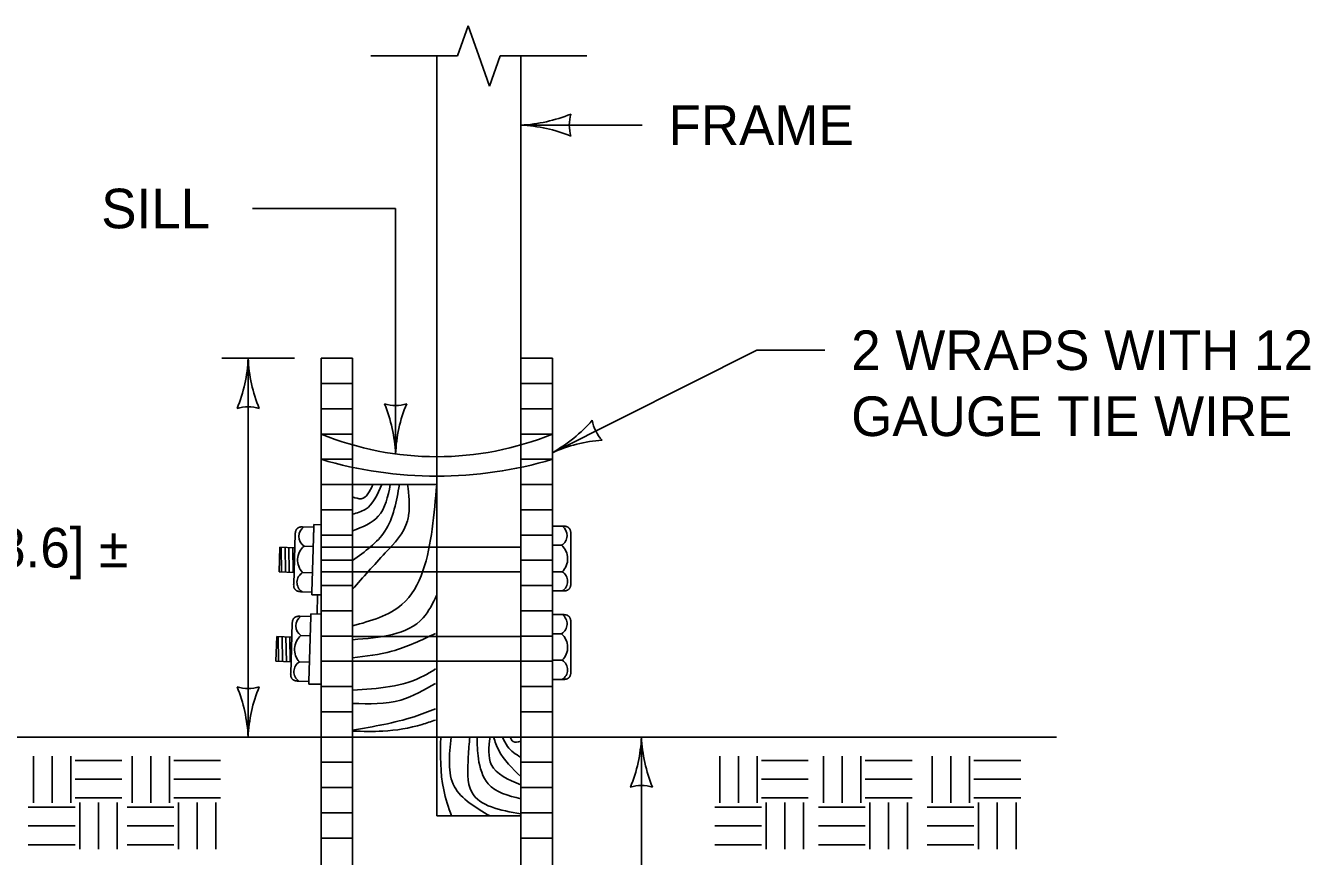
# Model space of a CAD drawing. Extents: x 49991.4 to 50021, y 49987.6 to 50011.4.
# Drawn here: x 50010.642 to 50012.589, y 49992.32 to 49993.578 of the extents above; entities that cross this region are included whole.
import ezdxf

# ---------------------------------------------------------------- set-up
doc = ezdxf.new("R2010")
doc.units = 0
for name, color, linetype in [('Level 1', 7, 'Continuous'), ('Level 2', 7, 'Continuous'), ('Level 3', 7, 'Continuous'), ('Level 4', 7, 'Continuous'), ('Level 6', 7, 'Continuous')]:
    doc.layers.add(name, color=color, linetype=linetype)

msp = doc.modelspace()

# ---------------------------------------------------------------- linework, layer by layer
at = {"layer": 'Level 1'}
for p, q in [((50011.265, 49992.8828), (50011.265, 49993.5322)), ((50011.3925, 49993.0741), (50011.3925, 49993.5322)), ((50011.1376, 49993.0741), (50011.0897, 49993.0741)), ((50011.0897, 49993.0741), (50011.0898, 49991.5441)), ((50011.1376, 49993.0741), (50011.0898, 49993.0741)), ((50011.1376, 49993.0741), (50011.1376, 49991.5441)), ((50011.3925, 49993.0741), (50011.3925, 49991.5441)), ((50011.4403, 49993.0741), (50011.3925, 49993.0741)), ((50011.4403, 49993.0741), (50011.4403, 49991.5441)), ((50011.1376, 49993.0358), (50011.0897, 49993.0358)), ((50011.4403, 49993.0358), (50011.3925, 49993.0358)), ((50011.1376, 49992.9976), (50011.0897, 49992.9976)), ((50011.4403, 49992.9976), (50011.3925, 49992.9976)), ((50011.1376, 49992.9593), (50011.0897, 49992.9593)), ((50011.4403, 49992.9593), (50011.3925, 49992.9593)), ((50011.1376, 49992.9211), (50011.0897, 49992.9211)), ((50011.4403, 49992.9211), (50011.3925, 49992.9211)), ((50011.265, 49992.8828), (50011.0897, 49992.8828)), ((50011.1376, 49992.8828), (50011.0898, 49992.8828)), ((50011.265, 49992.5003), (50011.265, 49992.8828)), ((50011.4403, 49992.8828), (50011.3925, 49992.8828)), ((50011.1376, 49992.8446), (50011.0897, 49992.8446)), ((50011.4403, 49992.8446), (50011.3925, 49992.8446)), ((50011.079, 49992.8225), (50011.0788, 49992.8181)), ((50011.079, 49992.8223), (50011.0897, 49992.8219)), ((50011.4403, 49992.8334), (50011.4403, 49992.5245)), ((50011.4403, 49992.8198), (50011.4403, 49992.7217)), ((50011.4572, 49992.8198), (50011.4403, 49992.8198)), ((50011.0482, 49992.7319), (50011.0506, 49992.808)), ((50011.0618, 49992.8188), (50011.0788, 49992.8181)), ((50011.0788, 49992.8181), (50011.0758, 49992.72)), ((50011.0785, 49992.8101), (50011.0783, 49992.8099)), ((50011.1376, 49992.8063), (50011.0897, 49992.8063)), ((50011.4403, 49992.8063), (50011.3925, 49992.8063)), ((50011.4682, 49992.7326), (50011.4682, 49992.8087)), ((50011.0272, 49992.7878), (50011.026, 49992.7504)), ((50011.0499, 49992.7871), (50011.0272, 49992.7878)), ((50011.0292, 49992.7877), (50011.0297, 49992.7503)), ((50011.0352, 49992.7876), (50011.0357, 49992.7501)), ((50011.0411, 49992.7874), (50011.0416, 49992.7499)), ((50011.0471, 49992.7872), (50011.0476, 49992.7497)), ((50011.0639, 49992.7896), (50011.0779, 49992.7891)), ((50011.4544, 49992.7909), (50011.4403, 49992.7909)), ((50011.1376, 49992.7681), (50011.0897, 49992.7681)), ((50011.4403, 49992.7681), (50011.3925, 49992.7681)), ((50011.0488, 49992.7497), (50011.026, 49992.7504)), ((50011.0767, 49992.749), (50011.0617, 49992.7495)), ((50011.4403, 49992.7506), (50011.4553, 49992.7506)), ((50011.1376, 49992.7298), (50011.0897, 49992.7298)), ((50011.4403, 49992.7298), (50011.3925, 49992.7298)), ((50011.4403, 49992.7217), (50011.4572, 49992.7217)), ((50011.0758, 49992.72), (50011.0588, 49992.7205)), ((50011.0758, 49992.72), (50011.0756, 49992.7157)), ((50011.0756, 49992.7157), (50011.0897, 49992.7158)), ((50011.084, 49992.6866), (50011.0845, 49992.7158)), ((50011.0573, 49992.6833), (50011.0743, 49992.6828)), ((50011.0743, 49992.6828), (50011.0712, 49992.5847)), ((50011.0744, 49992.687), (50011.0743, 49992.6828)), ((50011.0744, 49992.687), (50011.0897, 49992.6864)), ((50011.1376, 49992.6916), (50011.0897, 49992.6916)), ((50011.4403, 49992.6916), (50011.3925, 49992.6916)), ((50011.4403, 49992.6858), (50011.4403, 49992.5876)), ((50011.4572, 49992.6858), (50011.4403, 49992.6858)), ((50011.0437, 49992.5966), (50011.046, 49992.6727)), ((50011.4682, 49992.5986), (50011.4682, 49992.6748)), ((50011.0226, 49992.6525), (50011.0214, 49992.6151)), ((50011.0454, 49992.6518), (50011.0226, 49992.6525)), ((50011.0246, 49992.6524), (50011.0253, 49992.6149)), ((50011.0306, 49992.6523), (50011.0311, 49992.6147)), ((50011.0365, 49992.6521), (50011.0372, 49992.6145)), ((50011.0425, 49992.6519), (50011.043, 49992.6143)), ((50011.0593, 49992.6543), (50011.0734, 49992.6538)), ((50011.1376, 49992.6533), (50011.0897, 49992.6533)), ((50011.4403, 49992.6533), (50011.3925, 49992.6533)), ((50011.4544, 49992.6568), (50011.4403, 49992.6568)), ((50011.0442, 49992.6142), (50011.0214, 49992.6151)), ((50011.0721, 49992.6136), (50011.0571, 49992.6141)), ((50011.1376, 49992.6151), (50011.0897, 49992.6151)), ((50011.4403, 49992.6151), (50011.3925, 49992.6151)), ((50011.4403, 49992.6166), (50011.4553, 49992.6166)), ((50011.0712, 49992.5847), (50011.0542, 49992.5852)), ((50011.4403, 49992.5876), (50011.4572, 49992.5876)), ((50011.0712, 49992.5847), (50011.071, 49992.5804)), ((50011.071, 49992.5804), (50011.0897, 49992.5803)), ((50011.1376, 49992.5768), (50011.0897, 49992.5768)), ((50011.4403, 49992.5768), (50011.3925, 49992.5768)), ((50011.1376, 49992.5386), (50011.0897, 49992.5386)), ((50011.4403, 49992.5386), (50011.3925, 49992.5386)), ((50011.0897, 49992.5003), (50010.4249, 49992.5003)), ((50011.1376, 49992.5003), (50011.0897, 49992.5003)), ((50011.1376, 49992.5003), (50011.3925, 49992.5003)), ((50011.1376, 49992.5003), (50011.265, 49992.5003)), ((50011.265, 49992.5003), (50011.265, 49992.3808)), ((50012.2044, 49992.5003), (50011.3925, 49992.5003)), ((50010.6537, 49992.4715), (50010.6537, 49992.4006)), ((50010.682, 49992.4715), (50010.682, 49992.4006)), ((50010.7104, 49992.4715), (50010.7104, 49992.4006)), ((50010.8034, 49992.4715), (50010.8034, 49992.4006)), ((50010.8317, 49992.4715), (50010.8317, 49992.4006)), ((50010.8601, 49992.4715), (50010.8601, 49992.4006)), ((50011.6942, 49992.4715), (50011.6942, 49992.4006)), ((50011.7225, 49992.4715), (50011.7225, 49992.4006)), ((50011.7509, 49992.4715), (50011.7509, 49992.4006)), ((50011.8513, 49992.4715), (50011.8513, 49992.4006)), ((50011.8796, 49992.4715), (50011.8796, 49992.4006)), ((50011.908, 49992.4715), (50011.908, 49992.4006)), ((50012.0161, 49992.4715), (50012.0161, 49992.4006)), ((50012.0444, 49992.4715), (50012.0444, 49992.4006)), ((50012.0728, 49992.4715), (50012.0728, 49992.4006)), ((50010.7169, 49992.4649), (50010.7878, 49992.4649)), ((50010.8666, 49992.4649), (50010.9375, 49992.4649)), ((50011.1376, 49992.4621), (50011.0897, 49992.4621)), ((50011.4403, 49992.4621), (50011.3925, 49992.4621)), ((50011.7574, 49992.4649), (50011.8283, 49992.4649)), ((50011.9146, 49992.4649), (50011.9855, 49992.4649)), ((50012.0793, 49992.4649), (50012.1502, 49992.4649)), ((50010.7169, 49992.4366), (50010.7878, 49992.4366)), ((50010.8666, 49992.4366), (50010.9375, 49992.4366)), ((50011.7574, 49992.4366), (50011.8283, 49992.4366)), ((50011.9146, 49992.4366), (50011.9855, 49992.4366)), ((50012.0793, 49992.4366), (50012.1502, 49992.4366)), ((50011.1376, 49992.4238), (50011.0897, 49992.4238)), ((50011.4403, 49992.4238), (50011.3925, 49992.4238)), ((50010.646, 49992.394), (50010.7169, 49992.394)), ((50010.7169, 49992.4082), (50010.7878, 49992.4082)), ((50010.724, 49992.4011), (50010.724, 49992.3303)), ((50010.7524, 49992.4011), (50010.7524, 49992.3303)), ((50010.7808, 49992.4011), (50010.7808, 49992.3303)), ((50010.7957, 49992.394), (50010.8666, 49992.394)), ((50010.8666, 49992.4082), (50010.9375, 49992.4082)), ((50010.8737, 49992.4011), (50010.8737, 49992.3303)), ((50010.902, 49992.4011), (50010.902, 49992.3303)), ((50010.9304, 49992.4011), (50010.9304, 49992.3303)), ((50011.6865, 49992.394), (50011.7574, 49992.394)), ((50011.7574, 49992.4082), (50011.8283, 49992.4082)), ((50011.7645, 49992.4011), (50011.7645, 49992.3303)), ((50011.7928, 49992.4011), (50011.7928, 49992.3303)), ((50011.8212, 49992.4011), (50011.8212, 49992.3303)), ((50011.8437, 49992.394), (50011.9146, 49992.394)), ((50011.9146, 49992.4082), (50011.9855, 49992.4082)), ((50011.9216, 49992.4011), (50011.9216, 49992.3303)), ((50011.95, 49992.4011), (50011.95, 49992.3303)), ((50011.9784, 49992.4011), (50011.9784, 49992.3303)), ((50012.0084, 49992.394), (50012.0793, 49992.394)), ((50012.0793, 49992.4082), (50012.1502, 49992.4082)), ((50012.0864, 49992.4011), (50012.0864, 49992.3303)), ((50012.1147, 49992.4011), (50012.1147, 49992.3303)), ((50012.1431, 49992.4011), (50012.1431, 49992.3303)), ((50011.1376, 49992.3856), (50011.0897, 49992.3856)), ((50011.265, 49992.3808), (50011.3925, 49992.3808)), ((50011.4403, 49992.3856), (50011.3925, 49992.3856)), ((50010.646, 49992.3657), (50010.7169, 49992.3657)), ((50010.7957, 49992.3657), (50010.8666, 49992.3657)), ((50011.6865, 49992.3657), (50011.7574, 49992.3657)), ((50011.8437, 49992.3657), (50011.9146, 49992.3657)), ((50012.0084, 49992.3657), (50012.0793, 49992.3657)), ((50010.646, 49992.3373), (50010.7169, 49992.3373)), ((50010.7957, 49992.3373), (50010.8666, 49992.3373)), ((50011.1376, 49992.3473), (50011.0897, 49992.3473)), ((50011.4403, 49992.3473), (50011.3925, 49992.3473)), ((50011.6865, 49992.3373), (50011.7574, 49992.3373)), ((50011.8437, 49992.3373), (50011.9146, 49992.3373)), ((50012.0084, 49992.3373), (50012.0793, 49992.3373))]:
    msp.add_line(p, q, dxfattribs=at)
for centre, radius, start, end in [((50011.265, 49993.3896), 0.4646, 247.8325, 292.1683), ((50011.265, 49993.5086), 0.6131, 253.3872, 286.6139), ((50011.4453, 49992.8057), 0.0174, 301.3232, 53.9725), ((50011.0734, 49992.8042), 0.0174, 123.5225, 236.8488), ((50011.0818, 49992.7685), 0.0277, 130.2719, 223.4399), ((50011.4358, 49992.7703), 0.0277, 314.733, 47.9001), ((50011.0703, 49992.7347), 0.0171, 120.2654, 236.7716), ((50011.4462, 49992.7362), 0.0171, 302.0511, 57.9066), ((50011.0688, 49992.6688), 0.0174, 124.155, 236.8488), ((50011.4453, 49992.6717), 0.0174, 301.3232, 54.1519), ((50011.0772, 49992.6331), 0.0277, 130.2719, 223.4399), ((50011.4358, 49992.6363), 0.0277, 314.7309, 47.9001), ((50011.0657, 49992.5994), 0.0171, 120.2537, 236.3764), ((50011.4462, 49992.6021), 0.0171, 301.579, 57.9066)]:
    msp.add_arc(centre, radius, start, end, dxfattribs=at)
for points in [[(50011.1946, 49992.8828), (50011.1765, 49992.8347), (50011.1376, 49992.8128)], [(50011.2084, 49992.8828), (50011.1865, 49992.8123), (50011.1376, 49992.768)], [(50011.1819, 49992.8828), (50011.1566, 49992.8451), (50011.1376, 49992.8378)], [(50011.1684, 49992.8828), (50011.1507, 49992.8614), (50011.1376, 49992.8641)], [(50011.1376, 49992.7242), (50011.187, 49992.7792), (50011.2208, 49992.828), (50011.2225, 49992.8364), (50011.2208, 49992.8828)], [(50011.1376, 49992.6687), (50011.2124, 49992.701), (50011.2581, 49992.8154), (50011.265, 49992.8828)], [(50011.4572, 49992.8198), (50011.4578, 49992.8198), (50011.4584, 49992.8198), (50011.459, 49992.8198), (50011.4595, 49992.8198), (50011.46, 49992.8196), (50011.4606, 49992.8194), (50011.4611, 49992.8194), (50011.4616, 49992.8193), (50011.4621, 49992.8191), (50011.4624, 49992.8189), (50011.4629, 49992.8188), (50011.4634, 49992.8186), (50011.4638, 49992.8184), (50011.4641, 49992.8181), (50011.4645, 49992.8179), (50011.4648, 49992.8176), (50011.4652, 49992.8174), (50011.4655, 49992.817), (50011.4658, 49992.8167), (50011.466, 49992.8164), (50011.4663, 49992.816), (50011.4667, 49992.8157), (50011.4668, 49992.8154), (50011.467, 49992.8148), (50011.4672, 49992.8145), (50011.4674, 49992.814), (50011.4675, 49992.8136), (50011.4677, 49992.8131), (50011.4679, 49992.8126), (50011.4679, 49992.8121), (50011.468, 49992.8116), (50011.4682, 49992.8111), (50011.4682, 49992.8106), (50011.4682, 49992.8099), (50011.4682, 49992.8094), (50011.4682, 49992.8087)], [(50011.0618, 49992.8188), (50011.0613, 49992.8188), (50011.0607, 49992.8186), (50011.0602, 49992.8188), (50011.0596, 49992.8186), (50011.0591, 49992.8186), (50011.0586, 49992.8186), (50011.0581, 49992.8184), (50011.0576, 49992.8182), (50011.0571, 49992.8181), (50011.0568, 49992.8181), (50011.0562, 49992.8179), (50011.0557, 49992.8177), (50011.0554, 49992.8174), (50011.055, 49992.8172), (50011.0545, 49992.817), (50011.0542, 49992.8167), (50011.0539, 49992.8165), (50011.0535, 49992.8162), (50011.0534, 49992.8159), (50011.053, 49992.8155), (50011.0528, 49992.8152), (50011.0523, 49992.8148), (50011.0522, 49992.8145), (50011.052, 49992.814), (50011.0518, 49992.8136), (50011.0516, 49992.8131), (50011.0515, 49992.8128), (50011.0513, 49992.8123), (50011.0511, 49992.8118), (50011.051, 49992.8114), (50011.0508, 49992.8108), (50011.0508, 49992.8102), (50011.0508, 49992.8097), (50011.0506, 49992.8092), (50011.0506, 49992.8086), (50011.0506, 49992.808)], [(50011.0588, 49992.7205), (50011.0583, 49992.7205), (50011.0576, 49992.7207), (50011.0571, 49992.7207), (50011.0566, 49992.7207), (50011.0561, 49992.7208), (50011.0556, 49992.721), (50011.055, 49992.7212), (50011.0545, 49992.7212), (50011.054, 49992.7213), (50011.0535, 49992.7215), (50011.0532, 49992.7217), (50011.0527, 49992.7218), (50011.0523, 49992.7222), (50011.052, 49992.7224), (50011.0516, 49992.7227), (50011.0513, 49992.723), (50011.051, 49992.7232), (50011.0506, 49992.7236), (50011.0505, 49992.7239), (50011.0501, 49992.7242), (50011.0498, 49992.7246), (50011.0496, 49992.7249), (50011.0494, 49992.7254), (50011.0493, 49992.7258), (50011.0491, 49992.7261), (50011.0488, 49992.7266), (50011.0486, 49992.7271), (50011.0486, 49992.7276), (50011.0484, 49992.7281), (50011.0484, 49992.7285), (50011.0482, 49992.729), (50011.0482, 49992.7297), (50011.0482, 49992.7302), (50011.0482, 49992.7307), (50011.0481, 49992.7312), (50011.0482, 49992.7319)], [(50011.4572, 49992.7217), (50011.4578, 49992.7217), (50011.4584, 49992.7217), (50011.459, 49992.7217), (50011.4595, 49992.7217), (50011.46, 49992.7218), (50011.4606, 49992.7218), (50011.4611, 49992.722), (50011.4616, 49992.7222), (50011.4621, 49992.7224), (50011.4624, 49992.7225), (50011.4629, 49992.7227), (50011.4634, 49992.7229), (50011.4638, 49992.723), (50011.4641, 49992.7234), (50011.4645, 49992.7236), (50011.4648, 49992.7239), (50011.4652, 49992.7241), (50011.4655, 49992.7244), (50011.4658, 49992.7247), (50011.466, 49992.7251), (50011.4663, 49992.7254), (50011.4667, 49992.7258), (50011.4668, 49992.7261), (50011.467, 49992.7266), (50011.4672, 49992.727), (50011.4674, 49992.7275), (50011.4675, 49992.7278), (50011.4677, 49992.7283), (50011.4679, 49992.7288), (50011.4679, 49992.7293), (50011.468, 49992.7298), (50011.4682, 49992.7304), (50011.4682, 49992.7309), (50011.4682, 49992.7315), (50011.4682, 49992.732), (50011.4682, 49992.7326)], [(50011.1376, 49992.6478), (50011.2446, 49992.6809), (50011.2654, 49992.7158)], [(50011.0573, 49992.6833), (50011.0568, 49992.6833), (50011.0562, 49992.6833), (50011.0556, 49992.6833), (50011.055, 49992.6833), (50011.0545, 49992.6831), (50011.054, 49992.6831), (50011.0535, 49992.6831), (50011.053, 49992.6829), (50011.0525, 49992.6828), (50011.0522, 49992.6826), (50011.0516, 49992.6824), (50011.0511, 49992.6822), (50011.0508, 49992.6821), (50011.0505, 49992.6819), (50011.05, 49992.6817), (50011.0496, 49992.6814), (50011.0493, 49992.681), (50011.0491, 49992.6807), (50011.0488, 49992.6805), (50011.0484, 49992.6802), (50011.0482, 49992.6799), (50011.0477, 49992.6795), (50011.0476, 49992.679), (50011.0474, 49992.6787), (50011.0472, 49992.6783), (50011.0471, 49992.6778), (50011.0469, 49992.6775), (50011.0467, 49992.677), (50011.0466, 49992.6765), (50011.0464, 49992.676), (50011.0462, 49992.6754), (50011.0462, 49992.6749), (50011.0462, 49992.6744), (50011.046, 49992.6737), (50011.046, 49992.6732), (50011.046, 49992.6727)], [(50011.4572, 49992.6858), (50011.4578, 49992.6858), (50011.4584, 49992.6857), (50011.459, 49992.6857), (50011.4595, 49992.6857), (50011.46, 49992.6855), (50011.4606, 49992.6855), (50011.4611, 49992.6853), (50011.4616, 49992.6852), (50011.4621, 49992.6852), (50011.4624, 49992.685), (50011.4629, 49992.6848), (50011.4634, 49992.6846), (50011.4638, 49992.6843), (50011.4641, 49992.6841), (50011.4645, 49992.6838), (50011.4648, 49992.6836), (50011.4652, 49992.6833), (50011.4655, 49992.683), (50011.4658, 49992.6826), (50011.466, 49992.6824), (50011.4663, 49992.6821), (50011.4667, 49992.6816), (50011.4668, 49992.6812), (50011.467, 49992.6809), (50011.4672, 49992.6804), (50011.4674, 49992.6801), (50011.4675, 49992.6796), (50011.4677, 49992.679), (50011.4679, 49992.6785), (50011.4679, 49992.678), (50011.468, 49992.6775), (50011.4682, 49992.677), (50011.4682, 49992.6765), (50011.4682, 49992.676), (50011.4682, 49992.6753), (50011.4682, 49992.6748)], [(50011.1376, 49992.6203), (50011.1972, 49992.6304), (50011.2632, 49992.6573)], [(50011.0542, 49992.5852), (50011.0537, 49992.5852), (50011.053, 49992.5853), (50011.0525, 49992.5853), (50011.052, 49992.5853), (50011.0515, 49992.5855), (50011.051, 49992.5855), (50011.0505, 49992.5857), (50011.05, 49992.5858), (50011.0494, 49992.586), (50011.0491, 49992.5862), (50011.0486, 49992.5864), (50011.0481, 49992.5865), (50011.0477, 49992.5869), (50011.0474, 49992.587), (50011.0471, 49992.5872), (50011.0467, 49992.5877), (50011.0464, 49992.5879), (50011.046, 49992.5882), (50011.0459, 49992.5886), (50011.0455, 49992.5889), (50011.0452, 49992.5892), (50011.045, 49992.5896), (50011.0448, 49992.5901), (50011.0447, 49992.5904), (50011.0445, 49992.5908), (50011.0443, 49992.5913), (50011.044, 49992.5916), (50011.044, 49992.5921), (50011.0438, 49992.5926), (50011.0438, 49992.5932), (50011.0437, 49992.5937), (50011.0437, 49992.5942), (50011.0437, 49992.5949), (50011.0437, 49992.5954), (50011.0435, 49992.5959), (50011.0437, 49992.5966)], [(50011.1376, 49992.5714), (50011.2463, 49992.5934), (50011.2632, 49992.6035)], [(50011.4572, 49992.5876), (50011.4578, 49992.5876), (50011.4584, 49992.5876), (50011.459, 49992.5876), (50011.4595, 49992.5878), (50011.46, 49992.5879), (50011.4606, 49992.5879), (50011.4611, 49992.5881), (50011.4616, 49992.5881), (50011.4621, 49992.5883), (50011.4624, 49992.5884), (50011.4629, 49992.5886), (50011.4634, 49992.5888), (50011.4638, 49992.5891), (50011.4641, 49992.5893), (50011.4645, 49992.5894), (50011.4648, 49992.5898), (50011.4652, 49992.59), (50011.4655, 49992.5905), (50011.4658, 49992.5906), (50011.466, 49992.591), (50011.4663, 49992.5913), (50011.4667, 49992.5917), (50011.4668, 49992.5922), (50011.467, 49992.5925), (50011.4672, 49992.5928), (50011.4674, 49992.5934), (50011.4675, 49992.5939), (50011.4677, 49992.5944), (50011.4679, 49992.5947), (50011.4679, 49992.5952), (50011.468, 49992.5957), (50011.4682, 49992.5964), (50011.4682, 49992.5969), (50011.4682, 49992.5974), (50011.4682, 49992.598), (50011.4682, 49992.5986)], [(50011.1376, 49992.5513), (50011.2107, 49992.5564), (50011.2632, 49992.5816)], [(50011.1376, 49992.511), (50011.231, 49992.5312), (50011.2632, 49992.5429)], [(50011.1376, 49992.5093), (50011.1836, 49992.5093), (50011.2429, 49992.5194), (50011.2632, 49992.5261)], [(50011.2712, 49992.5003), (50011.2756, 49992.4202), (50011.2875, 49992.3808)], [(50011.2869, 49992.5003), (50011.2919, 49992.4251), (50011.3458, 49992.3808)], [(50011.315, 49992.5003), (50011.3129, 49992.4706), (50011.3182, 49992.4166), (50011.3925, 49992.3839)], [(50011.3261, 49992.5003), (50011.3282, 49992.4675), (50011.3431, 49992.4295), (50011.3925, 49992.4067)], [(50011.3458, 49992.5003), (50011.3477, 49992.4585), (50011.3925, 49992.4277)], [(50011.3512, 49992.5003), (50011.3591, 49992.4799), (50011.3925, 49992.4408)], [(50011.3647, 49992.5003), (50011.3723, 49992.4861), (50011.3925, 49992.4695)], [(50011.3765, 49992.5003), (50011.3809, 49992.4934), (50011.3925, 49992.4942)]]:
    msp.add_spline(points, degree=3, dxfattribs=at)
at = {"layer": 'Level 3'}
for p, q in [((50011.3925, 49993.4273), (50011.5764, 49993.4273)), ((50011.2027, 49993.301), (50010.986, 49993.301)), ((50011.2027, 49992.9292), (50011.2027, 49993.301)), ((50011.0497, 49993.0741), (50010.9392, 49993.0741)), ((50010.9792, 49993.0741), (50010.9792, 49992.5003)), ((50011.7505, 49993.0863), (50011.4403, 49992.9311)), ((50011.8533, 49993.0863), (50011.7505, 49993.0863)), ((50011.5753, 49991.5441), (50011.5753, 49992.5003))]:
    msp.add_line(p, q, dxfattribs=at)
for centre, radius, start, end in [((50011.381, 49993.66), 0.233, 272.8273, 292.0772), ((50011.5207, 49993.4273), 0.0548, 162.1388, 197.8612), ((50011.3833, 49993.2052), 0.2223, 67.456, 87.6395), ((50010.7571, 49993.0833), 0.2223, 337.456, 357.6395), ((50011.2119, 49993.0856), 0.233, 182.8273, 202.0772), ((50010.9792, 49992.9459), 0.0548, 72.1388, 107.8612), ((50011.2027, 49993.0574), 0.0548, 252.1388, 287.8612), ((50010.97, 49992.9177), 0.233, 2.8273, 22.0772), ((50011.4248, 49992.92), 0.2223, 157.456, 177.6395), ((50011.3259, 49993.1341), 0.233, 299.4085, 318.6584), ((50011.555, 49992.9885), 0.0548, 188.72, 224.4424), ((50011.5315, 49992.7283), 0.2223, 94.0372, 114.2207), ((50010.9792, 49992.6285), 0.0548, 252.1388, 287.8612), ((50010.7465, 49992.4888), 0.233, 2.8273, 22.0772), ((50011.2013, 49992.4911), 0.2223, 157.456, 177.6395), ((50011.3532, 49992.5095), 0.2223, 337.456, 357.6395), ((50011.808, 49992.5118), 0.233, 182.8273, 202.0772), ((50011.5753, 49992.3721), 0.0548, 72.1388, 107.8612)]:
    msp.add_arc(centre, radius, start, end, dxfattribs=at)
at = {"layer": 'Level 4'}
for p, q in [((50011.0897, 49992.7878), (50011.3925, 49992.7878)), ((50011.0897, 49992.7508), (50011.3925, 49992.7508)), ((50011.1376, 49992.6525), (50011.3925, 49992.6525)), ((50011.0897, 49992.6153), (50011.3925, 49992.6153))]:
    msp.add_line(p, q, dxfattribs=at)
at = {"layer": 'Level 6'}
for p, q in [((50011.3125, 49993.5779), (50011.2963, 49993.5322)), ((50011.3125, 49993.5779), (50011.3287, 49993.5322)), ((50011.165, 49993.5322), (50011.2963, 49993.5322)), ((50011.3287, 49993.5322), (50011.3449, 49993.4865)), ((50011.3611, 49993.5322), (50011.3449, 49993.4865)), ((50011.3611, 49993.5322), (50011.4925, 49993.5322))]:
    msp.add_line(p, q, dxfattribs=at)

# ---------------------------------------------------------------- texts
at = {"layer": 'Level 2'}
for s, p in [('FRAME', (50011.6164, 49993.3973)), ('SILL', (50010.7565, 49993.271)), ('2 WRAPS WITH 12 ', (50011.8933, 49993.0563)), ('GAUGE TIE WIRE', (50011.8933, 49992.9563)), ('9" [228.6] ±', (50010.3903, 49992.7572))]:
    msp.add_text(s, height=0.06, dxfattribs=at).set_placement(p)

doc.saveas('drawing.dxf')
